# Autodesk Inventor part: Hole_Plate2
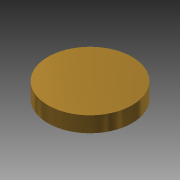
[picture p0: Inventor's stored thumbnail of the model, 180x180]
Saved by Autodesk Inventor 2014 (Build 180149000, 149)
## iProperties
Shininess: 64.0
Length Units: 11269
Angle Units: 11279
Time Units: 11290
Mass Units: 11283
Length Display Precision: 3
Angle Display Precision: 2
Created: 2002-08
Part Number: Hole_Plate2
Document SubType Name: Modeling
Designer: t_munrn
Density: 1 g/cm^3
Material: Generic
Appearance: Brass - Satin
Density: 0.0
Volumn: 0.0
Area: 0.0
PropertySet Name: Model Information
Control State: 0
Master: False
Checked Out: False
Author: t_munrn
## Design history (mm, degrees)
sketch "Sketch1"
  geometry: C1 r 32.5 at (0, 0); 1 further point
  constraints: 1 centre point, 1 coincident
  dimensions: "d0" = 65 diameter of C1
extrude "Extrusion1" new body sketch "Sketch1" distance "d1" = 12; taper "d2" = 0 deg
body "Solid1"
